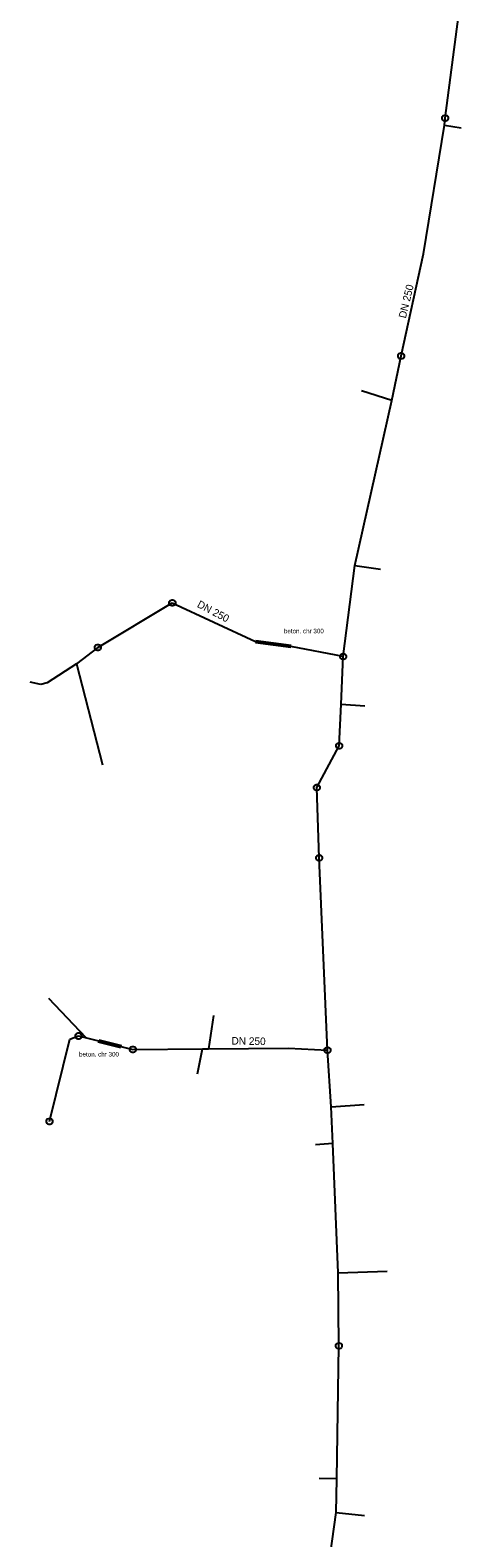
# Model space of a CAD drawing. Extents: x -717256 to -716843, y -1145423 to -1142840.
# Drawn here: x -717069.2 to -716996.7, y -1143755.3 to -1143505.2 of the extents above; entities that cross this region are included whole.
import ezdxf

# ---------------------------------------------------------------- set-up
doc = ezdxf.new("R2010")
doc.units = 0
for name, color, linetype in [('Vrstva 29', 7, 'Continuous'), ('Vrstva 30', 7, 'Continuous'), ('Vrstva 31', 7, 'Continuous')]:
    doc.layers.add(name, color=color, linetype=linetype)

msp = doc.modelspace()

# ---------------------------------------------------------------- linework, layer by layer
at = {"layer": 'Vrstva 29'}
for p, q in [((-717025.975, -1143607.625), (-717031.819, -1143606.841)), ((-717031.766, -1143606.444), (-717025.922, -1143607.228)), ((-717057.837, -1143672.692), (-717054.078, -1143673.619)), ((-717054.173, -1143674.007), (-717057.932, -1143673.08))]:
    msp.add_line(p, q, dxfattribs=at)
at = {"layer": 'Vrstva 30'}
for p, q in [((-717000.334, -1143519.778), (-716996.737, -1143492.566)), ((-717000.834, -1143519.678), (-717000.784, -1143519.528)), ((-717000.834, -1143519.878), (-717000.834, -1143519.678)), ((-717000.734, -1143520.128), (-717000.834, -1143519.878)), ((-717000.784, -1143519.528), (-717000.684, -1143519.378)), ((-717000.584, -1143520.228), (-717000.734, -1143520.128)), ((-717000.684, -1143519.378), (-717000.434, -1143519.278)), ((-717000.455, -1143520.952), (-717000.334, -1143519.778)), ((-717000.434, -1143519.278), (-717000.234, -1143519.278)), ((-717000.234, -1143519.278), (-716999.984, -1143519.378)), ((-716999.934, -1143520.128), (-717000.084, -1143520.228)), ((-716999.984, -1143519.378), (-716999.884, -1143519.528)), ((-716999.834, -1143519.878), (-716999.934, -1143520.128)), ((-716999.884, -1143519.528), (-716999.834, -1143519.678)), ((-716999.834, -1143519.678), (-716999.834, -1143519.878)), ((-717003.927, -1143542.32), (-717000.455, -1143520.952)), ((-717000.434, -1143520.278), (-717000.584, -1143520.228)), ((-717000.234, -1143520.278), (-717000.434, -1143520.278)), ((-717000.084, -1143520.228), (-717000.234, -1143520.278)), ((-717007.663, -1143559.247), (-717003.927, -1143542.32)), ((-717009.217, -1143566.632), (-717007.663, -1143559.247)), ((-717008.163, -1143559.147), (-717008.113, -1143558.997)), ((-717008.163, -1143559.347), (-717008.163, -1143559.147)), ((-717008.063, -1143559.597), (-717008.163, -1143559.347)), ((-717008.113, -1143558.997), (-717008.013, -1143558.847)), ((-717007.913, -1143559.697), (-717008.063, -1143559.597)), ((-717008.013, -1143558.847), (-717007.763, -1143558.747)), ((-717007.763, -1143559.747), (-717007.913, -1143559.697)), ((-717007.763, -1143558.747), (-717007.563, -1143558.747)), ((-717007.563, -1143559.747), (-717007.763, -1143559.747)), ((-717007.563, -1143558.747), (-717007.313, -1143558.847)), ((-717007.413, -1143559.697), (-717007.563, -1143559.747)), ((-717007.263, -1143559.597), (-717007.413, -1143559.697)), ((-717007.313, -1143558.847), (-717007.213, -1143558.997)), ((-717007.163, -1143559.347), (-717007.263, -1143559.597)), ((-717007.213, -1143558.997), (-717007.163, -1143559.147)), ((-717007.163, -1143559.147), (-717007.163, -1143559.347)), ((-717015.307, -1143593.996), (-717009.217, -1143566.632)), ((-717017.272, -1143609.116), (-717015.307, -1143593.996)), ((-717057.997, -1143607.596), (-717045.623, -1143600.215)), ((-717046.123, -1143600.115), (-717046.073, -1143599.965)), ((-717046.123, -1143600.315), (-717046.123, -1143600.115)), ((-717046.073, -1143599.965), (-717045.973, -1143599.815)), ((-717045.973, -1143599.815), (-717045.723, -1143599.715)), ((-717045.723, -1143599.715), (-717045.523, -1143599.715)), ((-717045.623, -1143600.215), (-717031.793, -1143606.643)), ((-717045.523, -1143599.715), (-717045.273, -1143599.815)), ((-717045.273, -1143599.815), (-717045.173, -1143599.965)), ((-717045.173, -1143599.965), (-717045.123, -1143600.115)), ((-717045.123, -1143600.115), (-717045.123, -1143600.315)), ((-717046.023, -1143600.565), (-717046.123, -1143600.315)), ((-717045.873, -1143600.665), (-717046.023, -1143600.565)), ((-717045.723, -1143600.715), (-717045.873, -1143600.665)), ((-717045.523, -1143600.715), (-717045.723, -1143600.715)), ((-717045.373, -1143600.665), (-717045.523, -1143600.715)), ((-717045.223, -1143600.565), (-717045.373, -1143600.665)), ((-717045.123, -1143600.315), (-717045.223, -1143600.565)), ((-717058.497, -1143607.496), (-717058.447, -1143607.346)), ((-717058.497, -1143607.696), (-717058.497, -1143607.496)), ((-717058.397, -1143607.946), (-717058.497, -1143607.696)), ((-717058.447, -1143607.346), (-717058.347, -1143607.196)), ((-717058.347, -1143607.196), (-717058.097, -1143607.096)), ((-717058.097, -1143607.096), (-717057.897, -1143607.096)), ((-717057.897, -1143607.096), (-717057.647, -1143607.196)), ((-717057.647, -1143607.196), (-717057.547, -1143607.346)), ((-717057.497, -1143607.696), (-717057.597, -1143607.946)), ((-717057.547, -1143607.346), (-717057.497, -1143607.496)), ((-717057.497, -1143607.496), (-717057.497, -1143607.696)), ((-717031.793, -1143606.643), (-717025.949, -1143607.427)), ((-717017.272, -1143609.116), (-717025.949, -1143607.427)), ((-717058.247, -1143608.046), (-717058.397, -1143607.946)), ((-717058.097, -1143608.096), (-717058.247, -1143608.046)), ((-717057.897, -1143608.096), (-717058.097, -1143608.096)), ((-717057.747, -1143608.046), (-717057.897, -1143608.096)), ((-717057.597, -1143607.946), (-717057.747, -1143608.046)), ((-717017.772, -1143609.016), (-717017.722, -1143608.866)), ((-717017.772, -1143609.216), (-717017.772, -1143609.016)), ((-717017.672, -1143609.466), (-717017.772, -1143609.216)), ((-717017.722, -1143608.866), (-717017.622, -1143608.716)), ((-717017.522, -1143609.566), (-717017.672, -1143609.466)), ((-717017.622, -1143608.716), (-717017.372, -1143608.616)), ((-717017.61, -1143617.026), (-717017.272, -1143609.116)), ((-717017.372, -1143609.616), (-717017.522, -1143609.566)), ((-717017.372, -1143608.616), (-717017.172, -1143608.616)), ((-717017.172, -1143609.616), (-717017.372, -1143609.616)), ((-717017.172, -1143608.616), (-717016.922, -1143608.716)), ((-717017.022, -1143609.566), (-717017.172, -1143609.616)), ((-717016.872, -1143609.466), (-717017.022, -1143609.566)), ((-717016.922, -1143608.716), (-717016.822, -1143608.866)), ((-717016.772, -1143609.216), (-717016.872, -1143609.466)), ((-717016.822, -1143608.866), (-717016.772, -1143609.016)), ((-717016.772, -1143609.016), (-717016.772, -1143609.216)), ((-717017.931, -1143623.928), (-717017.61, -1143617.026)), ((-717021.632, -1143630.85), (-717017.931, -1143623.928)), ((-717018.431, -1143623.828), (-717018.381, -1143623.678)), ((-717018.431, -1143624.028), (-717018.431, -1143623.828)), ((-717018.331, -1143624.278), (-717018.431, -1143624.028)), ((-717018.381, -1143623.678), (-717018.281, -1143623.528)), ((-717018.181, -1143624.378), (-717018.331, -1143624.278)), ((-717018.281, -1143623.528), (-717018.031, -1143623.428)), ((-717018.031, -1143624.428), (-717018.181, -1143624.378)), ((-717018.031, -1143623.428), (-717017.831, -1143623.428)), ((-717017.831, -1143624.428), (-717018.031, -1143624.428)), ((-717017.831, -1143623.428), (-717017.581, -1143623.528)), ((-717017.681, -1143624.378), (-717017.831, -1143624.428)), ((-717017.531, -1143624.278), (-717017.681, -1143624.378)), ((-717017.581, -1143623.528), (-717017.481, -1143623.678)), ((-717017.431, -1143624.028), (-717017.531, -1143624.278)), ((-717017.481, -1143623.678), (-717017.431, -1143623.828)), ((-717017.431, -1143623.828), (-717017.431, -1143624.028)), ((-717022.132, -1143630.75), (-717022.082, -1143630.6)), ((-717022.132, -1143630.95), (-717022.132, -1143630.75)), ((-717022.032, -1143631.2), (-717022.132, -1143630.95)), ((-717022.082, -1143630.6), (-717021.982, -1143630.45)), ((-717021.882, -1143631.3), (-717022.032, -1143631.2)), ((-717021.982, -1143630.45), (-717021.732, -1143630.35)), ((-717021.732, -1143631.35), (-717021.882, -1143631.3)), ((-717021.732, -1143630.35), (-717021.532, -1143630.35)), ((-717021.532, -1143631.35), (-717021.732, -1143631.35)), ((-717021.253, -1143642.517), (-717021.632, -1143630.85)), ((-717021.532, -1143630.35), (-717021.282, -1143630.45)), ((-717021.382, -1143631.3), (-717021.532, -1143631.35)), ((-717021.232, -1143631.2), (-717021.382, -1143631.3)), ((-717021.282, -1143630.45), (-717021.182, -1143630.6)), ((-717021.132, -1143630.95), (-717021.232, -1143631.2)), ((-717021.182, -1143630.6), (-717021.132, -1143630.75)), ((-717021.132, -1143630.75), (-717021.132, -1143630.95)), ((-717021.753, -1143642.417), (-717021.703, -1143642.267)), ((-717021.753, -1143642.617), (-717021.753, -1143642.417)), ((-717021.653, -1143642.867), (-717021.753, -1143642.617)), ((-717021.703, -1143642.267), (-717021.603, -1143642.117)), ((-717021.603, -1143642.117), (-717021.353, -1143642.017)), ((-717021.353, -1143642.017), (-717021.153, -1143642.017)), ((-717019.867, -1143674.417), (-717021.253, -1143642.517)), ((-717021.153, -1143642.017), (-717020.903, -1143642.117)), ((-717020.903, -1143642.117), (-717020.803, -1143642.267)), ((-717020.753, -1143642.617), (-717020.853, -1143642.867)), ((-717020.803, -1143642.267), (-717020.753, -1143642.417)), ((-717020.753, -1143642.417), (-717020.753, -1143642.617)), ((-717021.503, -1143642.967), (-717021.653, -1143642.867)), ((-717021.353, -1143643.017), (-717021.503, -1143642.967)), ((-717021.153, -1143643.017), (-717021.353, -1143643.017)), ((-717021.003, -1143642.967), (-717021.153, -1143643.017)), ((-717020.853, -1143642.867), (-717021.003, -1143642.967)), ((-717066.023, -1143686.231), (-717062.653, -1143672.575)), ((-717062.653, -1143672.575), (-717061.204, -1143672.068)), ((-717061.704, -1143671.968), (-717061.654, -1143671.818)), ((-717061.704, -1143672.168), (-717061.704, -1143671.968)), ((-717061.604, -1143672.418), (-717061.704, -1143672.168)), ((-717061.654, -1143671.818), (-717061.554, -1143671.668)), ((-717061.454, -1143672.518), (-717061.604, -1143672.418)), ((-717061.554, -1143671.668), (-717061.304, -1143671.568)), ((-717061.304, -1143672.568), (-717061.454, -1143672.518)), ((-717061.304, -1143671.568), (-717061.104, -1143671.568)), ((-717061.104, -1143672.568), (-717061.304, -1143672.568)), ((-717061.204, -1143672.068), (-717052.179, -1143674.294)), ((-717061.104, -1143671.568), (-717060.854, -1143671.668)), ((-717060.954, -1143672.518), (-717061.104, -1143672.568)), ((-717060.804, -1143672.418), (-717060.954, -1143672.518)), ((-717060.854, -1143671.668), (-717060.754, -1143671.818)), ((-717060.704, -1143672.168), (-717060.804, -1143672.418)), ((-717060.754, -1143671.818), (-717060.704, -1143671.968)), ((-717060.704, -1143671.968), (-717060.704, -1143672.168)), ((-717052.679, -1143674.194), (-717052.629, -1143674.044)), ((-717052.679, -1143674.394), (-717052.679, -1143674.194)), ((-717052.579, -1143674.644), (-717052.679, -1143674.394)), ((-717052.629, -1143674.044), (-717052.529, -1143673.894)), ((-717052.429, -1143674.744), (-717052.579, -1143674.644)), ((-717052.529, -1143673.894), (-717052.279, -1143673.794)), ((-717052.279, -1143674.794), (-717052.429, -1143674.744)), ((-717052.279, -1143673.794), (-717052.079, -1143673.794)), ((-717052.079, -1143674.794), (-717052.279, -1143674.794)), ((-717052.179, -1143674.294), (-717040.638, -1143674.194)), ((-717052.079, -1143673.794), (-717051.829, -1143673.894)), ((-717051.929, -1143674.744), (-717052.079, -1143674.794)), ((-717051.779, -1143674.644), (-717051.929, -1143674.744)), ((-717051.829, -1143673.894), (-717051.729, -1143674.044)), ((-717051.679, -1143674.394), (-717051.779, -1143674.644)), ((-717051.729, -1143674.044), (-717051.679, -1143674.194)), ((-717051.679, -1143674.194), (-717051.679, -1143674.394)), ((-717040.638, -1143674.194), (-717039.599, -1143674.185)), ((-717039.599, -1143674.185), (-717026.32, -1143674.07)), ((-717026.32, -1143674.07), (-717019.867, -1143674.417)), ((-717020.367, -1143674.317), (-717020.317, -1143674.167)), ((-717020.367, -1143674.517), (-717020.367, -1143674.317)), ((-717020.267, -1143674.767), (-717020.367, -1143674.517)), ((-717020.317, -1143674.167), (-717020.217, -1143674.017)), ((-717020.117, -1143674.867), (-717020.267, -1143674.767)), ((-717020.217, -1143674.017), (-717019.967, -1143673.917)), ((-717019.967, -1143674.917), (-717020.117, -1143674.867)), ((-717019.967, -1143673.917), (-717019.767, -1143673.917)), ((-717019.767, -1143674.917), (-717019.967, -1143674.917)), ((-717019.27, -1143683.8), (-717019.867, -1143674.417)), ((-717019.767, -1143673.917), (-717019.517, -1143674.017)), ((-717019.617, -1143674.867), (-717019.767, -1143674.917)), ((-717019.467, -1143674.767), (-717019.617, -1143674.867)), ((-717019.517, -1143674.017), (-717019.417, -1143674.167)), ((-717019.367, -1143674.517), (-717019.467, -1143674.767)), ((-717019.417, -1143674.167), (-717019.367, -1143674.317)), ((-717019.367, -1143674.317), (-717019.367, -1143674.517)), ((-717019, -1143689.919), (-717019.27, -1143683.8)), ((-717066.523, -1143686.131), (-717066.473, -1143685.981)), ((-717066.523, -1143686.331), (-717066.523, -1143686.131)), ((-717066.423, -1143686.581), (-717066.523, -1143686.331)), ((-717066.473, -1143685.981), (-717066.373, -1143685.831)), ((-717066.273, -1143686.681), (-717066.423, -1143686.581)), ((-717066.373, -1143685.831), (-717066.123, -1143685.731)), ((-717066.123, -1143686.731), (-717066.273, -1143686.681)), ((-717066.123, -1143685.731), (-717065.923, -1143685.731)), ((-717065.923, -1143686.731), (-717066.123, -1143686.731)), ((-717065.923, -1143685.731), (-717065.673, -1143685.831)), ((-717065.773, -1143686.681), (-717065.923, -1143686.731)), ((-717065.623, -1143686.581), (-717065.773, -1143686.681)), ((-717065.673, -1143685.831), (-717065.573, -1143685.981)), ((-717065.523, -1143686.331), (-717065.623, -1143686.581)), ((-717065.573, -1143685.981), (-717065.523, -1143686.131)), ((-717065.523, -1143686.131), (-717065.523, -1143686.331)), ((-717018.071, -1143711.345), (-717019, -1143689.919)), ((-717017.962, -1143723.473), (-717018.071, -1143711.345)), ((-717018.462, -1143723.373), (-717018.412, -1143723.223)), ((-717018.462, -1143723.573), (-717018.462, -1143723.373)), ((-717018.362, -1143723.823), (-717018.462, -1143723.573)), ((-717018.412, -1143723.223), (-717018.312, -1143723.073)), ((-717018.212, -1143723.923), (-717018.362, -1143723.823)), ((-717018.332, -1143745.563), (-717017.962, -1143723.473)), ((-717018.312, -1143723.073), (-717018.062, -1143722.973)), ((-717018.062, -1143723.973), (-717018.212, -1143723.923)), ((-717018.062, -1143722.973), (-717017.862, -1143722.973)), ((-717017.862, -1143723.973), (-717018.062, -1143723.973)), ((-717017.862, -1143722.973), (-717017.612, -1143723.073)), ((-717017.712, -1143723.923), (-717017.862, -1143723.973)), ((-717017.562, -1143723.823), (-717017.712, -1143723.923)), ((-717017.612, -1143723.073), (-717017.512, -1143723.223)), ((-717017.462, -1143723.573), (-717017.562, -1143723.823)), ((-717017.512, -1143723.223), (-717017.462, -1143723.373)), ((-717017.462, -1143723.373), (-717017.462, -1143723.573)), ((-717018.456, -1143751.123), (-717018.332, -1143745.563)), ((-717020.525, -1143766.418), (-717018.456, -1143751.123))]:
    msp.add_line(p, q, dxfattribs=at)
at = {"layer": 'Vrstva 31'}
for p, q in [((-717000.455, -1143520.952), (-716997.655, -1143521.39)), ((-717009.217, -1143566.632), (-717014.243, -1143565.037)), ((-717015.307, -1143593.996), (-717011.057, -1143594.606)), ((-717057.997, -1143607.596), (-717061.554, -1143610.304)), ((-717061.554, -1143610.304), (-717066.384, -1143613.474)), ((-717061.554, -1143610.304), (-717057.226, -1143627.074)), ((-717067.424, -1143613.733), (-717069.224, -1143613.393)), ((-717066.384, -1143613.474), (-717067.424, -1143613.733)), ((-717017.61, -1143617.026), (-717013.669, -1143617.295)), ((-717059.912, -1143672.386), (-717066.133, -1143665.862)), ((-717038.808, -1143668.669), (-717039.599, -1143674.185)), ((-717041.472, -1143678.354), (-717040.638, -1143674.194)), ((-717019.27, -1143683.8), (-717013.758, -1143683.422)), ((-717019, -1143689.919), (-717021.887, -1143690.124)), ((-717018.071, -1143711.345), (-717009.988, -1143711.103)), ((-717018.332, -1143745.563), (-717021.227, -1143745.499)), ((-717018.456, -1143751.123), (-717013.739, -1143751.596))]:
    msp.add_line(p, q, dxfattribs=at)

# ---------------------------------------------------------------- texts
at = {"layer": 'Vrstva 30'}
for rotation, p in [(76.5, (-717006.869, -1143553.079)), (332.1, (-717041.62, -1143600.842)), (359.1, (-717035.811, -1143673.489))]:
    msp.add_text('DN 250', height=1.25, rotation=rotation, dxfattribs=at).set_placement(p)
for p in [(-717027.104, -1143605.254), (-717061.103, -1143675.472)]:
    msp.add_text('beton. chr 300', height=0.74999, dxfattribs=at).set_placement(p)

doc.saveas('drawing.dxf')
